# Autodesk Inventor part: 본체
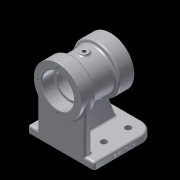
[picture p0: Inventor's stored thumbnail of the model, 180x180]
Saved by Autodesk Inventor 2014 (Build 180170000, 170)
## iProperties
Created: 2020-06
Part Number: 본체
Material: Aluminum 6061
Document SubType Name: Modeling
Designer: kh
Mass: 726.812 g
Surface Area: 640.48 cm^2
Volume: 268.196 cm^3
Density: 2.71 g/cm^3
Appearance: Aluminum - Flat
Author: kh
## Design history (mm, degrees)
sketch "Sketch1"
  geometry: L1 (24.5, 0)-(35, 0); L2 (35, 0)-(35, -22); L3 (35, -22)-(29, -22); L4 (29, -22)-(29, -56); L5 (29, -56)-(35, -56); L6 (35, -56)-(35, -78); L7 (35, -78)-(24.5, -78); L8 (0, -78)-(0, 0); L9 (23.5, -1)-(23.5, -17.7); L10 (23.2, -18)-(20, -18); L11 (20, -18)-(20, -24); L12 (20, -24)-(20, -24); L13 (23, -27)-(23, -51); L14 (20, -54)-(20, -54); L15 (20, -54)-(20, -60); L16 (20, -60)-(23.2, -60); L17 (23.5, -60.3)-(23.5, -77); L18 (23.5, -1)-(24.5, 0); L19 (23.5, -77)-(24.5, -78); A1 r 0.3 centre (23.2, -60.3) between (23.5, -60.3) and (23.2, -60); A2 r 0.3 centre (23.2, -17.7) between (23.2, -18) and (23.5, -17.7); A3 r 3 centre (20, -27) between (23, -27) and (20, -24); A4 r 3 centre (20, -51) between (20, -54) and (23, -51); 4 further points
  constraints: 38 end point, 10 parallel, 10 point on line, 8 point on circle, 8 tangent, 5 perpendicular, 4 centre point, 2 equal radius, 1 collinear, 1 horizontal
  dimensions: "d6" = 70 diameter of L2 L8; "d7" = 78 distance between parallel lines of L7 L1; "d8" = 22 distance of L5.end L6.end; "d9" = 22 distance of L1.end L2.end; "d10" = 70 diameter of L6 L8; "d11" = 58 diameter of L4 L8; "d12" = 47 diameter of L9 L8; "d13" = 47 diameter of L17 L8; "d14" = 40 diameter of L11 L8; "d15" = 40 diameter of L15 L8; "d16" = 46 diameter of L13 L8; "d17" = 18 distance between parallel lines of L1 L10; "d18" = 6 distance between parallel lines of L12 L10; "d19" = 30 distance between parallel lines of L14 L12; "d20" = 18 distance between parallel lines of L7 L16; "d21" = 1 distance of L9.start point (23.5, 0); "d22" = 45 deg angle of L9 L18; "d23" = 1 distance of L17.end point (23.5, -78) (= d21); "d24" = 45 deg angle of L17 L19 (= d22); "d25" = 0.3 radius of A1; "d26" = 3 radius of A3
revolve "Revolution1" sketch "Sketch1" stored, may be unused: angle "d27" = 90 deg
workplane "Work Plane1"
workplane "Work Plane2"
sketch "Sketch2"
  geometry: L1 (49, -5)-(-49, -5); L2 (-49, -5)-(-49, -75); L3 (-29, -95)-(29, -95); L4 (49, -75)-(49, -5); C1 r 4.5 at (29, -75); C2 r 4.5 at (29, -39); C3 r 4.5 at (-29, -75); C4 r 4.5 at (-29, -39); A1 r 20 centre (29, -75) between (29, -95) and (49, -75); A2 r 20 centre (-29, -75) between (-49, -75) and (-29, -95); 3 further points
  constraints: 8 end point, 6 centre point, 4 point on circle, 4 point on line, 4 tangent, 2 parallel, 1 equal radius, 1 horizontal, 1 perpendicular
  dimensions: "d30" = 5 distance from line of point (0, 0) L1; "d31" = 90 distance of point (49, -95) L1.start; "d32" = 98 distance of point (-49, -95) point (49, -95); "d33" = 49 distance from line of point (0, 0) L4; "d34" = 9 diameter of C1; "d35" = 70 distance from line of L1 C1.centre; "d36" = 9 diameter of C2; "d37" = 36 distance of C1.centre C2.centre; "d38" = 9 diameter of C3; "d39" = 9 diameter of C4; "d40" = 70 distance from line of L1 C3.centre; "d41" = 36 distance of C3.centre C4.centre; "d42" = 58 distance of C1.centre C3.centre; "d43" = 29 horizontal distance of point (0, 0) C2.centre; "d44" = 29 horizontal distance of point (0, 0) C1.centre; "d45" = 29 horizontal distance of point (0, 0) C4.centre; "d46" = 20 radius of A1
extrude "Extrusion1" join sketch "Sketch2" distance "d47" = 10; taper "d48" = 0 deg
fillet "Fillet1" dims "d49" = 3
sketch "Sketch3"
  geometry: L1 (-46, 5)-(46, 5) reference; L2 (-35, 5)-(35, 5); L3 (35, 5)-(35, 15); L4 (35, 15)-(-35, 15); L5 (-35, 15)-(-35, 5); 1 further point
  constraints: 8 end point, 2 parallel, 1 horizontal, 1 perpendicular, 1 point on line
  dimensions: "d50" = 70 distance between parallel lines of L3 L5; "d51" = 35 distance from line of point (0, 0) L5; "d52" = 10 distance between parallel lines of L2 L4
extrude "Extrusion2" join sketch "Sketch3" stored distance "d53" = 10; taper "d54" = 0 deg
sketch "Sketch4"
  geometry: L1 (-28.008, -66.671)-(-72.872, -83); L2 (-72.872, -83)-(-72.872, -13.378); L3 (-72.872, -13.378)-(-28.008, -13.378); L4 (-28.008, -13.378)-(-28.008, -66.671); L5 (-80, -95)-(-73, -95) reference; 1 further point
  constraints: 8 end point, 2 perpendicular, 1 vertical
  dimensions: "d55" = 70 deg angle of L2 L1; "d56" = 12 distance from line of L5 L1.end
extrude "Extrusion3" join sketch "Sketch4" stored distance "d57" = 10; taper "d58" = 0 deg
workplane "Work Plane3"
sketch "Sketch5"
  geometry: L1 (-35, 0)-(35, 0) reference; C1 r 6 at (0, -39); 2 further points
  constraints: 1 centre point, 1 midpoint, 1 vertical alignment
  dimensions: "d60" = 12 diameter of C1; "d61" = 39 distance from line of L1 C1.centre
extrude "Extrusion4" join sketch "Sketch5" stored distance "d62" = 3; taper "d63" = 0 deg
hole "Hole1" diameter "d66" = 5.188; stored, may be unused: countersink angle "d70" = 90 deg, drill point angle "d72" = 118 deg; dims "d64" = 10, "d65" = 10, "d67" = 15, "d68" = 4, "d69" = 2, "d71" = 15
fillet "Fillet2" dims "d73" = 3
fillet "Fillet3" dims "d74" = 3
sketch "Sketch6"
  geometry: L1 (-67, 0)-(0, 0) reference; L2 (-70, 7)-(-70, 0) reference; 2 further points
  constraints: 1 other
  dimensions: "d75" = 45 distance from line of L2 point (-25, 4); "d76" = 4 distance from line of L1 point (-25, 4)
emboss "Emboss1" sketch "Sketch6" dims "d77" = 0.5, "d78" = 0
sketch "Sketch7" dims "d79" = 57
  geometry: C1 r 35 at (0, 0) reference; 2 further points
  constraints: 2 vertical alignment, 1 coincident, 2 other
hole "Hole2" sketch "Sketch7" at (0, 28.5) diameter "d80" = 3.242; stored, may be unused: countersink angle "d84" = 90 deg, drill point angle "d86" = 118 deg; dims "d81" = 10, "d82" = 4, "d83" = 2, "d85" = 12
pattern_circular "Circular Pattern1" dims angle "d88" = 360 deg
sketch "Sketch8" dims "d90" = 57
  geometry: C1 r 24.5 at (0, 0) reference; 2 further points
  constraints: 2 vertical alignment, 1 coincident, 2 other
hole "Hole3" sketch "Sketch8" at (0, 28.5) diameter "d91" = 3.242; stored, may be unused: countersink angle "d95" = 90 deg, drill point angle "d97" = 118 deg; dims "d92" = 10, "d93" = 4, "d94" = 2, "d96" = 12
pattern_circular "Circular Pattern2" dims angle "d99" = 360 deg
body "Solid1"
other parameters: "d29" = -5, "d59" = 31
